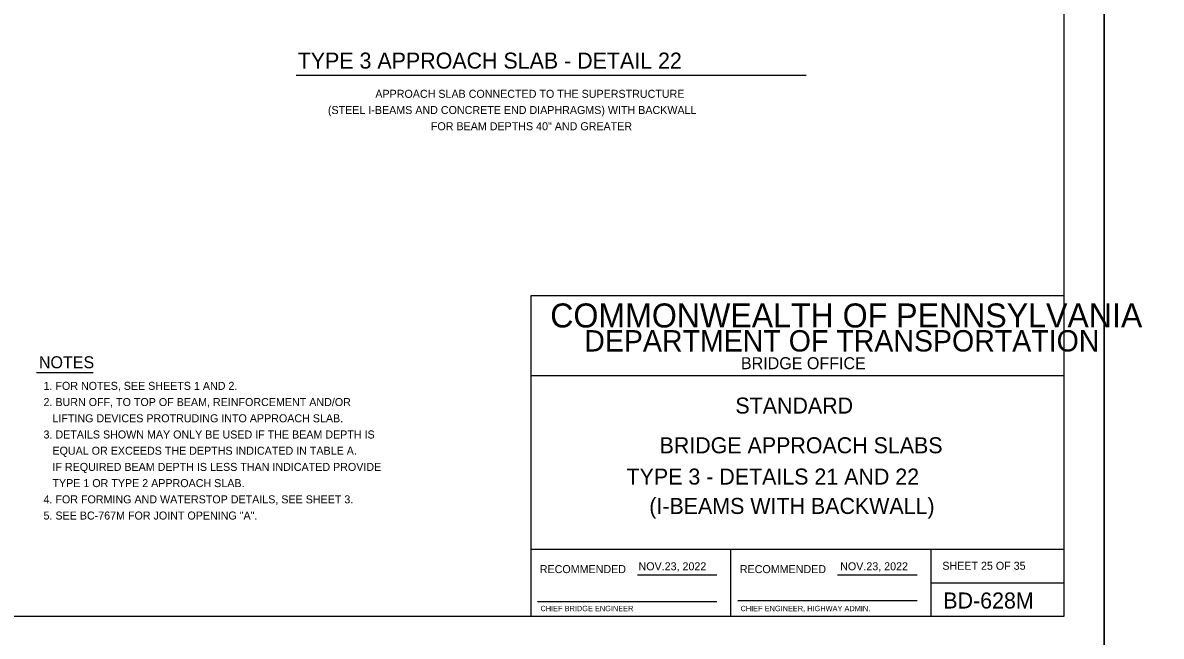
# Model space of a CAD drawing. Extents: x 636530 to 644067, y 294168 to 299122.
# Drawn here: x 639442.3 to 639869.1, y 295364 to 295593.7 of the extents above; entities that cross this region are included whole.
import ezdxf

# ---------------------------------------------------------------- set-up
doc = ezdxf.new("R2010")
doc.units = 0
for name, color, linetype in [('1', 7, 'Continuous'), ('DATES', 7, 'Continuous'), ('PLT-BNDY', 7, 'Continuous'), ('SIGNATORY TITLES', 7, 'Continuous')]:
    doc.layers.add(name, color=color, linetype=linetype)

msp = doc.modelspace()

# ---------------------------------------------------------------- linework, layer by layer
at = {"layer": '1'}
for p, q in [((639832.78, 295371.48), (639832.78, 295935.48)), ((639544.73, 295574.13), (639736.02, 295574.13)), ((639832.78, 295491.48), (639632.78, 295491.48)), ((639632.78, 295491.48), (639632.78, 295371.48)), ((639832.78, 295371.48), (639832.78, 295491.48)), ((639447.4, 295462.7), (639468.64, 295462.7)), ((639832.78, 295461.48), (639632.78, 295461.48)), ((639832.78, 295396.48), (639632.78, 295396.48)), ((639707.79, 295371.47), (639707.79, 295396.48)), ((639782.78, 295396.48), (639782.78, 295371.48)), ((639672.75, 295386.98), (639702.51, 295386.98)), ((639747.75, 295386.98), (639777.65, 295386.98)), ((639782.78, 295383.98), (639832.78, 295383.98)), ((639635.28, 295376.98), (639702.51, 295376.98)), ((639710.41, 295377.35), (639777.65, 295377.35)), ((639046.78, 295371.48), (639832.78, 295371.48)), ((639632.78, 295371.48), (639832.78, 295371.48))]:
    msp.add_line(p, q, dxfattribs=at)
at = {"layer": 'PLT-BNDY'}
for points in [[(639006.78, 295950.48), (639847.78, 295950.48), (639847.78, 295356.48), (639006.78, 295356.48)], [(639847.78, 295950.48), (640688.78, 295950.48), (640688.78, 295356.48), (639847.78, 295356.48)]]:
    msp.add_lwpolyline(points, close=True, dxfattribs=at)

# ---------------------------------------------------------------- texts
at = {"layer": '1'}
for s, height, p in [('TYPE 3 APPROACH SLAB - DETAIL 22', 6, (639545.35, 295576.55)), ('APPROACH SLAB CONNECTED TO THE SUPERSTRUCTURE', 3, (639574.45, 295565.61)), ('(STEEL I-BEAMS AND CONCRETE END DIAPHRAGMS) WITH BACKWALL', 3, (639556.67, 295559.54)), ('FOR BEAM DEPTHS 40" AND GREATER', 3, (639595.28, 295553.47)), ('COMMONWEALTH OF PENNSYLVANIA', 9, (639640.03, 295479.6)), ('DEPARTMENT OF TRANSPORTATION', 8.0002, (639652.78, 295470.6)), ('NOTES', 4.5, (639448.3, 295464.32)), ('STANDARD', 6, (639709.45, 295447.36)), ('BRIDGE APPROACH SLABS', 6.0001, (639681.02, 295432.48)), ('TYPE 3 - DETAILS 21 AND 22', 6.0001, (639668.64, 295420.76)), ('(I-BEAMS WITH BACKWALL)', 6.0001, (639677.16, 295409.76)), ('RECOMMENDED', 3.0002, (639636.12, 295387.6)), ('RECOMMENDED', 3.0002, (639711.12, 295387.6)), ('BD-628M', 6, (639787.41, 295374.35))]:
    msp.add_text(s, height=height, rotation=360, dxfattribs=at).set_placement(p)
for s, height, p in [('BRIDGE OFFICE', 4.5, (639711.53, 295463.98)), ('1. FOR NOTES, SEE SHEETS 1 AND 2.', 3, (639450.04, 295456.24)), ('2. BURN OFF, TO TOP OF BEAM, REINFORCEMENT AND/OR', 3, (639450.04, 295450.17)), ('   LIFTING DEVICES PROTRUDING INTO APPROACH SLAB.', 3, (639450.04, 295444.09)), ('3. DETAILS SHOWN MAY ONLY BE USED IF THE BEAM DEPTH IS', 3, (639450.04, 295438.02)), ('   EQUAL OR EXCEEDS THE DEPTHS INDICATED IN TABLE A.', 3, (639450.04, 295431.95)), ('   IF REQUIRED BEAM DEPTH IS LESS THAN INDICATED PROVIDE', 3, (639450.04, 295425.88)), ('   TYPE 1 OR TYPE 2 APPROACH SLAB.', 3, (639450.04, 295419.81)), ('4. FOR FORMING AND WATERSTOP DETAILS, SEE SHEET 3.', 3, (639450.04, 295413.73)), ('5. SEE BC-767M FOR JOINT OPENING "A".', 3, (639450.04, 295407.66)), ('SHEET 25 OF 35', 3, (639787.04, 295388.86))]:
    msp.add_text(s, height=height, dxfattribs=at).set_placement(p)
at = {"layer": 'DATES'}
for p in [(639673.12, 295388.66), (639748.74, 295388.66)]:
    msp.add_text('NOV.23, 2022', height=3, dxfattribs=at).set_placement(p)
at = {"layer": 'SIGNATORY TITLES'}
for s, p in [('CHIEF BRIDGE ENGINEER', (639636.37, 295373.35)), ('CHIEF ENGINEER, HIGHWAY ADMIN.', (639711.37, 295373.35))]:
    msp.add_text(s, height=2, dxfattribs=at).set_placement(p)

doc.saveas('drawing.dxf')
